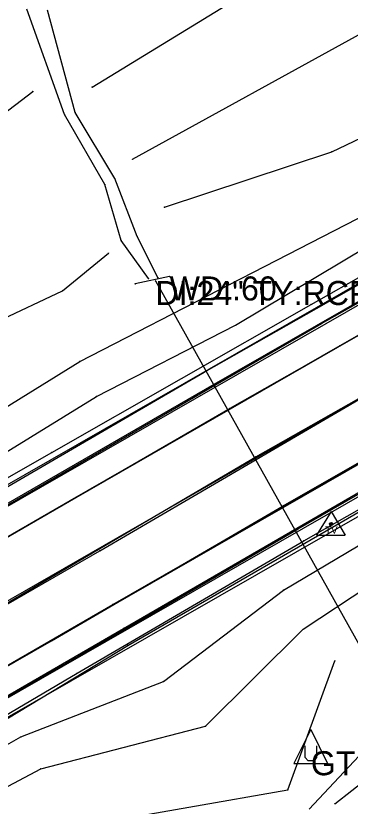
# Model space of a CAD drawing. Extents: x 1419505 to 1434054, y 1956910 to 1968644.
# Drawn here: x 1421892.8 to 1421962.4, y 1958243.6 to 1958407.8 of the extents above; entities that cross this region are included whole.
import ezdxf

# ---------------------------------------------------------------- set-up
doc = ezdxf.new("R2010")
doc.units = 0
for name, color, linetype in [('S_BREAKLINE', 7, 'Continuous'), ('S_CROSS_DRAIN', 7, 'Continuous'), ('S_CROSS_DRAIN_ANNOT', 7, 'Continuous'), ('S_DITCHLINE', 7, 'Continuous'), ('S_DRG_PT_SYM', 7, 'Continuous'), ('S_EDGE_PAVEMENT', 7, 'Continuous'), ('S_GRD_PT_SYM', 7, 'Continuous'), ('S_HEADWALL', 7, 'Continuous'), ('S_HEADWALL_ANNOT', 7, 'Continuous'), ('S_MSC_PT_SYM', 7, 'Continuous'), ('S_PAVEMENT_CROWN', 7, 'Continuous'), ('S_RDW_PT_SYM', 7, 'Continuous'), ('S_SECONDARY_CTL', 7, 'Continuous'), ('S_SHOULDER', 7, 'Continuous'), ('S_UTILITY_POLE', 7, 'Continuous'), ('S_UTILITY_POLE_ANNOT', 7, 'Continuous')]:
    doc.layers.add(name, color=color, linetype=linetype)

msp = doc.modelspace()

# ---------------------------------------------------------------- linework, layer by layer
at = {"layer": 'S_BREAKLINE'}
for p, q in [((1422234.7195, 1958507.1234), (1421697.9208, 1958199.8056)), ((1422256.1529, 1958471.0691), (1421717.7711, 1958162.8162)), ((1421908.6574, 1958393.0361), (1421954.8464, 1958421.2319)), ((1421917.104, 1958378.0281), (1421994.628, 1958420.6969)), ((1421885.3899, 1958383.7635), (1421896.3546, 1958392.116)), ((1421958.5247, 1958379.5882), (1421978.0419, 1958388.8168)), ((1421954.2254, 1958347.8811), (1422017.6015, 1958383.6815)), ((1421923.7444, 1958368.0655), (1421958.5247, 1958379.5882)), ((1421937.4223, 1958352.1054), (1421979.78, 1958373.9038)), ((1421938.5364, 1958343.5369), (1421982.2072, 1958369.6576)), ((1421931.9739, 1958333.7802), (1421983.2653, 1958362.8431)), ((1421902.488, 1958350.6643), (1421912.1097, 1958358.5418)), ((1421906.1123, 1958336.0104), (1421937.4223, 1958352.1054)), ((1421844.6403, 1958323.4146), (1421902.488, 1958350.6643)), ((1421900.2859, 1958317.0992), (1421954.2254, 1958347.8811)), ((1421909.5655, 1958328.7239), (1421938.5364, 1958343.5369)), ((1421850.8607, 1958301.8422), (1421906.1123, 1958336.0104)), ((1421885.4349, 1958306.7545), (1421931.9739, 1958333.7802)), ((1421854.841, 1958295.0667), (1421909.5655, 1958328.7239)), ((1421952.7093, 1958298.741), (1422001.1034, 1958326.2257)), ((1421848.0885, 1958287.2632), (1421900.2859, 1958317.0992)), ((1421916.0939, 1958277.0146), (1421981.5771, 1958314.819)), ((1421948.47, 1958288.4943), (1421976.2538, 1958304.9524)), ((1421905.5902, 1958271.2752), (1421952.7093, 1958298.741)), ((1421952.6123, 1958280.3578), (1421981.8452, 1958299.808)), ((1421923.5064, 1958269.5311), (1421948.47, 1958288.4943)), ((1421932.282, 1958260.2455), (1421952.6123, 1958280.3578)), ((1421865.6917, 1958246.4556), (1421916.0939, 1958277.0146)), ((1421949.3751, 1958247.0146), (1421959.1947, 1958273.8174)), ((1421858.4792, 1958243.4524), (1421905.5902, 1958271.2752)), ((1421893.8825, 1958258.0443), (1421923.5064, 1958269.5311)), ((1421897.9767, 1958251.4039), (1421932.282, 1958260.2455)), ((1421858.9662, 1958238.0111), (1421893.8825, 1958258.0443)), ((1421953.8624, 1958242.9624), (1421967.2182, 1958257.3113)), ((1421862.4755, 1958232.3747), (1421897.9767, 1958251.4039)), ((1421908.1844, 1958239.8192), (1421949.3751, 1958247.0146))]:
    msp.add_line(p, q, dxfattribs=at)
at = {"layer": 'S_CROSS_DRAIN'}
msp.add_line((1421921.8453, 1958352.7455), (1421964.179, 1958277.2576), dxfattribs=at)
at = {"layer": 'S_DITCHLINE'}
for p, q in [((1421902.9591, 1958387.3657), (1421895.0836, 1958409.2291)), ((1421905.1512, 1958387.7727), (1421899.3698, 1958409.0011)), ((1421913.3787, 1958374.0018), (1421905.1512, 1958387.7727)), ((1421911.3246, 1958372.8018), (1421902.9591, 1958387.3657)), ((1421914.6998, 1958361.177), (1421911.3246, 1958372.8018)), ((1421918.025, 1958362.0051), (1421913.3787, 1958374.0018)), ((1421920.4112, 1958353.2835), (1421914.6998, 1958361.177)), ((1421922.3243, 1958353.4515), (1421918.025, 1958362.0051)), ((1421959.2047, 1958244.1254), (1421972.3946, 1958254.4791))]:
    msp.add_line(p, q, dxfattribs=at)
at = {"layer": 'S_DRG_PT_SYM'}
msp.add_lwpolyline([(1421921.8453, 1958352.7455), (1421921.8453, 1958352.7955), (1421921.8453, 1958352.7455), (1421921.7953, 1958352.7455), (1421921.8453, 1958352.7455), (1421921.8453, 1958352.6955), (1421921.8453, 1958352.7455), (1421921.8953, 1958352.7455)], dxfattribs=at)
at = {"layer": 'S_EDGE_PAVEMENT'}
for p, q in [((1422239.4358, 1958499.3739), (1421702.5421, 1958191.435)), ((1422250.9195, 1958479.1606), (1421712.8678, 1958170.5937)), ((1421960.3158, 1958339.3426), (1422022.2428, 1958375.1419)), ((1421937.4303, 1958326.3088), (1421986.8895, 1958354.4306)), ((1421904.1381, 1958307.0935), (1421960.3158, 1958339.3426)), ((1421948.429, 1958305.9944), (1421997.4022, 1958334.0293)), ((1421888.7252, 1958298.1849), (1421937.4303, 1958326.3088)), ((1421913.0017, 1958285.5141), (1421972.0725, 1958319.4363)), ((1421852.5588, 1958277.4456), (1421904.1381, 1958307.0935)), ((1421900.2339, 1958277.9816), (1421948.429, 1958305.9944)), ((1421862.1364, 1958256.1602), (1421913.0017, 1958285.5141)), ((1421855.613, 1958252.494), (1421900.2339, 1958277.9816))]:
    msp.add_line(p, q, dxfattribs=at)
at = {"layer": 'S_GRD_PT_SYM'}
for points in [[(1421908.6574, 1958393.0361), (1421908.6574, 1958393.0861), (1421908.6574, 1958393.0361), (1421908.6074, 1958393.0361), (1421908.6574, 1958393.0361), (1421908.6574, 1958392.9861), (1421908.6574, 1958393.0361), (1421908.7074, 1958393.0361)], [(1421896.3546, 1958392.116), (1421896.3546, 1958392.166), (1421896.3546, 1958392.116), (1421896.3046, 1958392.116), (1421896.3546, 1958392.116), (1421896.3546, 1958392.066), (1421896.3546, 1958392.116), (1421896.4046, 1958392.116)], [(1421902.9591, 1958387.3657), (1421902.9591, 1958387.4157), (1421902.9591, 1958387.3657), (1421902.9091, 1958387.3657), (1421902.9591, 1958387.3657), (1421902.9591, 1958387.3157), (1421902.9591, 1958387.3657), (1421903.0091, 1958387.3657)], [(1421905.1512, 1958387.7727), (1421905.1512, 1958387.8227), (1421905.1512, 1958387.7727), (1421905.1012, 1958387.7727), (1421905.1512, 1958387.7727), (1421905.1512, 1958387.7227), (1421905.1512, 1958387.7727), (1421905.2012, 1958387.7727)], [(1421958.5247, 1958379.5882), (1421958.5247, 1958379.6382), (1421958.5247, 1958379.5882), (1421958.4747, 1958379.5882), (1421958.5247, 1958379.5882), (1421958.5247, 1958379.5382), (1421958.5247, 1958379.5882), (1421958.5747, 1958379.5882)], [(1421917.104, 1958378.0281), (1421917.104, 1958378.0781), (1421917.104, 1958378.0281), (1421917.054, 1958378.0281), (1421917.104, 1958378.0281), (1421917.104, 1958377.9781), (1421917.104, 1958378.0281), (1421917.154, 1958378.0281)], [(1421911.3246, 1958372.8018), (1421911.3246, 1958372.8518), (1421911.3246, 1958372.8018), (1421911.2746, 1958372.8018), (1421911.3246, 1958372.8018), (1421911.3246, 1958372.7518), (1421911.3246, 1958372.8018), (1421911.3746, 1958372.8018)], [(1421913.3787, 1958374.0018), (1421913.3787, 1958374.0518), (1421913.3787, 1958374.0018), (1421913.3287, 1958374.0018), (1421913.3787, 1958374.0018), (1421913.3787, 1958373.9518), (1421913.3787, 1958374.0018), (1421913.4287, 1958374.0018)], [(1421923.7444, 1958368.0655), (1421923.7444, 1958368.1155), (1421923.7444, 1958368.0655), (1421923.6944, 1958368.0655), (1421923.7444, 1958368.0655), (1421923.7444, 1958368.0155), (1421923.7444, 1958368.0655), (1421923.7944, 1958368.0655)], [(1421914.6998, 1958361.177), (1421914.6998, 1958361.227), (1421914.6998, 1958361.177), (1421914.6498, 1958361.177), (1421914.6998, 1958361.177), (1421914.6998, 1958361.127), (1421914.6998, 1958361.177), (1421914.7498, 1958361.177)], [(1421918.025, 1958362.0051), (1421918.025, 1958362.0551), (1421918.025, 1958362.0051), (1421917.975, 1958362.0051), (1421918.025, 1958362.0051), (1421918.025, 1958361.9551), (1421918.025, 1958362.0051), (1421918.075, 1958362.0051)], [(1421912.1097, 1958358.5418), (1421912.1097, 1958358.5918), (1421912.1097, 1958358.5418), (1421912.0597, 1958358.5418), (1421912.1097, 1958358.5418), (1421912.1097, 1958358.4918), (1421912.1097, 1958358.5418), (1421912.1597, 1958358.5418)], [(1421920.4112, 1958353.2835), (1421920.4112, 1958353.3335), (1421920.4112, 1958353.2835), (1421920.3612, 1958353.2835), (1421920.4112, 1958353.2835), (1421920.4112, 1958353.2335), (1421920.4112, 1958353.2835), (1421920.4612, 1958353.2835)], [(1421922.3243, 1958353.4515), (1421922.3243, 1958353.5015), (1421922.3243, 1958353.4515), (1421922.2743, 1958353.4515), (1421922.3243, 1958353.4515), (1421922.3243, 1958353.4015), (1421922.3243, 1958353.4515), (1421922.3743, 1958353.4515)], [(1421937.4223, 1958352.1054), (1421937.4223, 1958352.1554), (1421937.4223, 1958352.1054), (1421937.3723, 1958352.1054), (1421937.4223, 1958352.1054), (1421937.4223, 1958352.0554), (1421937.4223, 1958352.1054), (1421937.4723, 1958352.1054)], [(1421902.488, 1958350.6643), (1421902.488, 1958350.7143), (1421902.488, 1958350.6643), (1421902.438, 1958350.6643), (1421902.488, 1958350.6643), (1421902.488, 1958350.6143), (1421902.488, 1958350.6643), (1421902.538, 1958350.6643)], [(1421954.2254, 1958347.8811), (1421954.2254, 1958347.9311), (1421954.2254, 1958347.8811), (1421954.1754, 1958347.8811), (1421954.2254, 1958347.8811), (1421954.2254, 1958347.8311), (1421954.2254, 1958347.8811), (1421954.2754, 1958347.8811)], [(1421938.5364, 1958343.5369), (1421938.5364, 1958343.5869), (1421938.5364, 1958343.5369), (1421938.4864, 1958343.5369), (1421938.5364, 1958343.5369), (1421938.5364, 1958343.4869), (1421938.5364, 1958343.5369), (1421938.5864, 1958343.5369)], [(1421906.1123, 1958336.0104), (1421906.1123, 1958336.0604), (1421906.1123, 1958336.0104), (1421906.0623, 1958336.0104), (1421906.1123, 1958336.0104), (1421906.1123, 1958335.9604), (1421906.1123, 1958336.0104), (1421906.1623, 1958336.0104)], [(1421931.9739, 1958333.7802), (1421931.9739, 1958333.8302), (1421931.9739, 1958333.7802), (1421931.9239, 1958333.7802), (1421931.9739, 1958333.7802), (1421931.9739, 1958333.7302), (1421931.9739, 1958333.7802), (1421932.0239, 1958333.7802)], [(1421909.5655, 1958328.7239), (1421909.5655, 1958328.7739), (1421909.5655, 1958328.7239), (1421909.5155, 1958328.7239), (1421909.5655, 1958328.7239), (1421909.5655, 1958328.6739), (1421909.5655, 1958328.7239), (1421909.6155, 1958328.7239)], [(1421900.2859, 1958317.0992), (1421900.2859, 1958317.1492), (1421900.2859, 1958317.0992), (1421900.2359, 1958317.0992), (1421900.2859, 1958317.0992), (1421900.2859, 1958317.0492), (1421900.2859, 1958317.0992), (1421900.3359, 1958317.0992)], [(1421952.7093, 1958298.741), (1421952.7093, 1958298.791), (1421952.7093, 1958298.741), (1421952.6593, 1958298.741), (1421952.7093, 1958298.741), (1421952.7093, 1958298.691), (1421952.7093, 1958298.741), (1421952.7593, 1958298.741)], [(1421948.47, 1958288.4943), (1421948.47, 1958288.5443), (1421948.47, 1958288.4943), (1421948.42, 1958288.4943), (1421948.47, 1958288.4943), (1421948.47, 1958288.4443), (1421948.47, 1958288.4943), (1421948.52, 1958288.4943)], [(1421952.6123, 1958280.3578), (1421952.6123, 1958280.4078), (1421952.6123, 1958280.3578), (1421952.5623, 1958280.3578), (1421952.6123, 1958280.3578), (1421952.6123, 1958280.3078), (1421952.6123, 1958280.3578), (1421952.6623, 1958280.3578)], [(1421916.0939, 1958277.0146), (1421916.0939, 1958277.0646), (1421916.0939, 1958277.0146), (1421916.0439, 1958277.0146), (1421916.0939, 1958277.0146), (1421916.0939, 1958276.9646), (1421916.0939, 1958277.0146), (1421916.1439, 1958277.0146)], [(1421959.1947, 1958273.8174), (1421959.1947, 1958273.8674), (1421959.1947, 1958273.8174), (1421959.1447, 1958273.8174), (1421959.1947, 1958273.8174), (1421959.1947, 1958273.7674), (1421959.1947, 1958273.8174), (1421959.2447, 1958273.8174)], [(1421905.5902, 1958271.2752), (1421905.5902, 1958271.3252), (1421905.5902, 1958271.2752), (1421905.5402, 1958271.2752), (1421905.5902, 1958271.2752), (1421905.5902, 1958271.2252), (1421905.5902, 1958271.2752), (1421905.6402, 1958271.2752)], [(1421923.5064, 1958269.5311), (1421923.5064, 1958269.5811), (1421923.5064, 1958269.5311), (1421923.4564, 1958269.5311), (1421923.5064, 1958269.5311), (1421923.5064, 1958269.4811), (1421923.5064, 1958269.5311), (1421923.5564, 1958269.5311)], [(1421932.282, 1958260.2455), (1421932.282, 1958260.2955), (1421932.282, 1958260.2455), (1421932.232, 1958260.2455), (1421932.282, 1958260.2455), (1421932.282, 1958260.1955), (1421932.282, 1958260.2455), (1421932.332, 1958260.2455)], [(1421893.8825, 1958258.0443), (1421893.8825, 1958258.0943), (1421893.8825, 1958258.0443), (1421893.8325, 1958258.0443), (1421893.8825, 1958258.0443), (1421893.8825, 1958257.9943), (1421893.8825, 1958258.0443), (1421893.9325, 1958258.0443)], [(1421897.9767, 1958251.4039), (1421897.9767, 1958251.4539), (1421897.9767, 1958251.4039), (1421897.9267, 1958251.4039), (1421897.9767, 1958251.4039), (1421897.9767, 1958251.3539), (1421897.9767, 1958251.4039), (1421898.0267, 1958251.4039)], [(1421949.3751, 1958247.0146), (1421949.3751, 1958247.0646), (1421949.3751, 1958247.0146), (1421949.3251, 1958247.0146), (1421949.3751, 1958247.0146), (1421949.3751, 1958246.9646), (1421949.3751, 1958247.0146), (1421949.4251, 1958247.0146)], [(1421959.2047, 1958244.1254), (1421959.2047, 1958244.1754), (1421959.2047, 1958244.1254), (1421959.1547, 1958244.1254), (1421959.2047, 1958244.1254), (1421959.2047, 1958244.0754), (1421959.2047, 1958244.1254), (1421959.2547, 1958244.1254)]]:
    msp.add_lwpolyline(points, dxfattribs=at)
at = {"layer": 'S_HEADWALL'}
msp.add_line((1421924.7925, 1958353.6895), (1421917.668, 1958352.1334), dxfattribs=at)
at = {"layer": 'S_MSC_PT_SYM'}
for points in [[(1421924.7925, 1958353.6895), (1421924.7925, 1958353.7395), (1421924.7925, 1958353.6895), (1421924.7425, 1958353.6895), (1421924.7925, 1958353.6895), (1421924.7925, 1958353.6395), (1421924.7925, 1958353.6895), (1421924.8425, 1958353.6895)], [(1421917.668, 1958352.1334), (1421917.668, 1958352.1834), (1421917.668, 1958352.1334), (1421917.618, 1958352.1334), (1421917.668, 1958352.1334), (1421917.668, 1958352.0834), (1421917.668, 1958352.1334), (1421917.718, 1958352.1334)]]:
    msp.add_lwpolyline(points, dxfattribs=at)
at = {"layer": 'S_PAVEMENT_CROWN'}
for p, q in [((1422245.2512, 1958489.5463), (1421708.2975, 1958181.3584)), ((1421942.7396, 1958316.2111), (1421991.6488, 1958343.8719)), ((1421910.2865, 1958296.6928), (1421965.8041, 1958329.0769)), ((1421894.4935, 1958287.8373), (1421942.7396, 1958316.2111)), ((1421857.7452, 1958266.3619), (1421910.2865, 1958296.6928)), ((1421850.4787, 1958262.1086), (1421894.4935, 1958287.8373))]:
    msp.add_line(p, q, dxfattribs=at)
at = {"layer": 'S_RDW_PT_SYM'}
for points in [[(1421956.4095, 1958343.8829), (1421956.4095, 1958343.9329), (1421956.4095, 1958343.8829), (1421956.3595, 1958343.8829), (1421956.4095, 1958343.8829), (1421956.4095, 1958343.8329), (1421956.4095, 1958343.8829), (1421956.4595, 1958343.8829)], [(1421960.3158, 1958339.3426), (1421960.3158, 1958339.3926), (1421960.3158, 1958339.3426), (1421960.2658, 1958339.3426), (1421960.3158, 1958339.3426), (1421960.3158, 1958339.2926), (1421960.3158, 1958339.3426), (1421960.3658, 1958339.3426)], [(1421934.0991, 1958331.3301), (1421934.0991, 1958331.3801), (1421934.0991, 1958331.3301), (1421934.0491, 1958331.3301), (1421934.0991, 1958331.3301), (1421934.0991, 1958331.2801), (1421934.0991, 1958331.3301), (1421934.1491, 1958331.3301)], [(1421937.4303, 1958326.3088), (1421937.4303, 1958326.3588), (1421937.4303, 1958326.3088), (1421937.3803, 1958326.3088), (1421937.4303, 1958326.3088), (1421937.4303, 1958326.2588), (1421937.4303, 1958326.3088), (1421937.4803, 1958326.3088)], [(1421942.7396, 1958316.2111), (1421942.7396, 1958316.2611), (1421942.7396, 1958316.2111), (1421942.6896, 1958316.2111), (1421942.7396, 1958316.2111), (1421942.7396, 1958316.1611), (1421942.7396, 1958316.2111), (1421942.7896, 1958316.2111)], [(1421901.321, 1958312.1168), (1421901.321, 1958312.1668), (1421901.321, 1958312.1168), (1421901.271, 1958312.1168), (1421901.321, 1958312.1168), (1421901.321, 1958312.0668), (1421901.321, 1958312.1168), (1421901.371, 1958312.1168)], [(1421904.1381, 1958307.0935), (1421904.1381, 1958307.1435), (1421904.1381, 1958307.0935), (1421904.0881, 1958307.0935), (1421904.1381, 1958307.0935), (1421904.1381, 1958307.0435), (1421904.1381, 1958307.0935), (1421904.1881, 1958307.0935)], [(1421948.429, 1958305.9944), (1421948.429, 1958306.0444), (1421948.429, 1958305.9944), (1421948.379, 1958305.9944), (1421948.429, 1958305.9944), (1421948.429, 1958305.9444), (1421948.429, 1958305.9944), (1421948.479, 1958305.9944)], [(1421951.5622, 1958301.2411), (1421951.5622, 1958301.2911), (1421951.5622, 1958301.2411), (1421951.5122, 1958301.2411), (1421951.5622, 1958301.2411), (1421951.5622, 1958301.1911), (1421951.5622, 1958301.2411), (1421951.6122, 1958301.2411)], [(1421910.2865, 1958296.6928), (1421910.2865, 1958296.7428), (1421910.2865, 1958296.6928), (1421910.2365, 1958296.6928), (1421910.2865, 1958296.6928), (1421910.2865, 1958296.6428), (1421910.2865, 1958296.6928), (1421910.3365, 1958296.6928)], [(1421894.4935, 1958287.8373), (1421894.4935, 1958287.8873), (1421894.4935, 1958287.8373), (1421894.4435, 1958287.8373), (1421894.4935, 1958287.8373), (1421894.4935, 1958287.7873), (1421894.4935, 1958287.8373), (1421894.5435, 1958287.8373)], [(1421913.0017, 1958285.5141), (1421913.0017, 1958285.5641), (1421913.0017, 1958285.5141), (1421912.9517, 1958285.5141), (1421913.0017, 1958285.5141), (1421913.0017, 1958285.4641), (1421913.0017, 1958285.5141), (1421913.0517, 1958285.5141)], [(1421915.1739, 1958280.4978), (1421915.1739, 1958280.5478), (1421915.1739, 1958280.4978), (1421915.1239, 1958280.4978), (1421915.1739, 1958280.4978), (1421915.1739, 1958280.4478), (1421915.1739, 1958280.4978), (1421915.2239, 1958280.4978)], [(1421900.2339, 1958277.9816), (1421900.2339, 1958278.0316), (1421900.2339, 1958277.9816), (1421900.1839, 1958277.9816), (1421900.2339, 1958277.9816), (1421900.2339, 1958277.9316), (1421900.2339, 1958277.9816), (1421900.2839, 1958277.9816)], [(1421903.2171, 1958273.2913), (1421903.2171, 1958273.3413), (1421903.2171, 1958273.2913), (1421903.1671, 1958273.2913), (1421903.2171, 1958273.2913), (1421903.2171, 1958273.2413), (1421903.2171, 1958273.2913), (1421903.2671, 1958273.2913)]]:
    msp.add_lwpolyline(points, dxfattribs=at)
at = {"layer": 'S_SECONDARY_CTL'}
for p, q in [((1421958.3847, 1958304.8623), (1421955.3747, 1958299.9084)), ((1421958.3847, 1958304.8623), (1421961.332, 1958299.9084)), ((1421955.3747, 1958299.9084), (1421961.332, 1958299.9084))]:
    msp.add_line(p, q, dxfattribs=at)
for radius in [0.3111, 0.1827, 0.1033]:
    msp.add_circle((1421958.3847, 1958302.2522), radius, dxfattribs=at)
at = {"layer": 'S_SHOULDER'}
for p, q in [((1422236.8876, 1958504.0772), (1421699.4589, 1958196.0923)), ((1422254.1918, 1958474.1573), (1421715.306, 1958165.4004)), ((1421956.4095, 1958343.8829), (1422019.2166, 1958379.5102)), ((1421934.0991, 1958331.3301), (1421984.7564, 1958360.397)), ((1421901.321, 1958312.1168), (1421956.4095, 1958343.8829)), ((1421886.292, 1958303.7623), (1421934.0991, 1958331.3301)), ((1421951.5622, 1958301.2411), (1421999.6003, 1958328.9599)), ((1421915.1739, 1958280.4978), (1421975.9918, 1958315.6651)), ((1421850.5827, 1958282.8619), (1421901.321, 1958312.1168)), ((1421903.2171, 1958273.2913), (1421951.5622, 1958301.2411)), ((1421864.5826, 1958251.2879), (1421915.1739, 1958280.4978)), ((1421857.6421, 1958247.1836), (1421903.2171, 1958273.2913))]:
    msp.add_line(p, q, dxfattribs=at)
at = {"layer": 'S_UTILITY_POLE'}
for p, q in [((1421954.1904, 1958259.5709), (1421950.6641, 1958252.4797)), ((1421954.1904, 1958259.5709), (1421957.6779, 1958252.4797)), ((1421952.9891, 1958253.7197), (1421952.9891, 1958256.1609)), ((1421955.3529, 1958256.1609), (1421955.3529, 1958253.7197)), ((1421953.6091, 1958253.0609), (1421952.9891, 1958253.7197)), ((1421954.8104, 1958253.0609), (1421953.6091, 1958253.0609)), ((1421955.3529, 1958253.7197), (1421954.8104, 1958253.0609)), ((1421950.6641, 1958252.4797), (1421957.6779, 1958252.4797))]:
    msp.add_line(p, q, dxfattribs=at)

# ---------------------------------------------------------------- texts
at = {"layer": 'S_CROSS_DRAIN_ANNOT'}
msp.add_text('DI:24" TY:RCP CN:0 LN:86.50 INV', height=5, dxfattribs=at).set_placement((1421921.8453, 1958347.7455))
at = {"layer": 'S_HEADWALL_ANNOT'}
msp.add_text('WD:.60', height=5, dxfattribs=at).set_placement((1421924.7925, 1958348.6895))
at = {"layer": 'S_SECONDARY_CTL'}
msp.add_text('TV', height=1.5, rotation=360, dxfattribs=at).set_placement((1421957.18, 1958300.2409))
at = {"layer": 'S_UTILITY_POLE_ANNOT'}
msp.add_text('GTE', height=5, dxfattribs=at).set_placement((1421954.1904, 1958250.0372))

doc.saveas('drawing.dxf')
